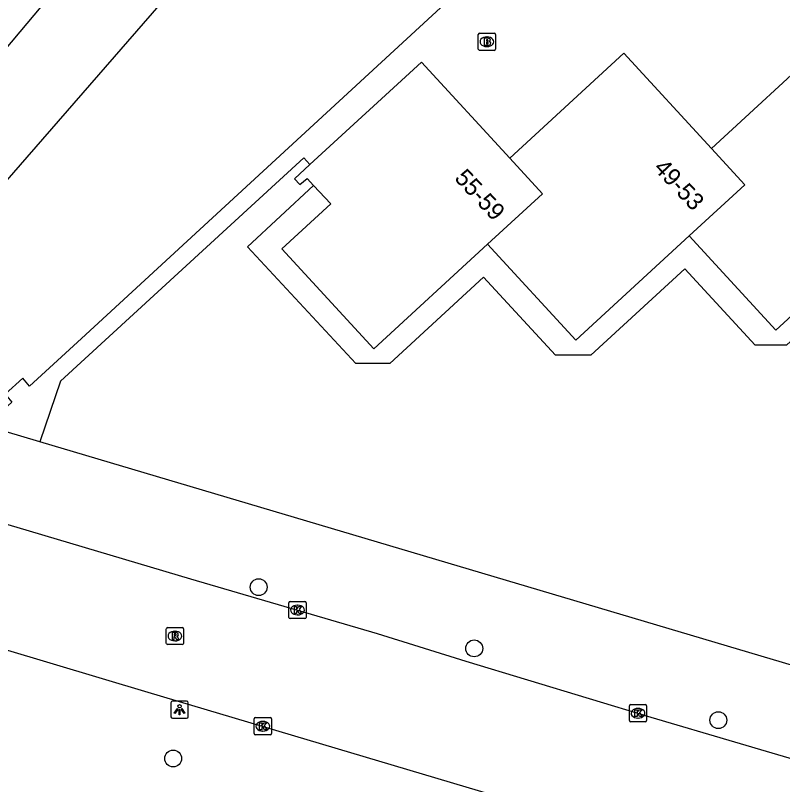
# Model space of a CAD drawing. Extents: x 160356 to 161355, y 381727 to 382845.
# Drawn here: x 160703.22 to 160747.73, y 381896.03 to 381940.67 of the extents above; entities that cross this region are included whole.
import ezdxf

# ---------------------------------------------------------------- set-up
doc = ezdxf.new("R2010")
doc.units = 0
for name, color, linetype in [('IMGEO_Boom', 7, 'Continuous'), ('IMGEO_Brandkraan', 7, 'Continuous'), ('IMGEO_Groenvoorziening', 7, 'Continuous'), ('IMGEO_Kolk', 7, 'Continuous'), ('IMGEO_Lichtpunt', 7, 'Continuous'), ('IMGEO_Pand', 7, 'Continuous'), ('IMGEO_Pand_nummerreeks', 7, 'Continuous'), ('IMGEO_Rijbaan_lokaal_open', 7, 'Continuous'), ('IMGEO_Rioolput', 7, 'Continuous'), ('IMGEO_Voetpad_halfverhard', 7, 'Continuous'), ('IMGEO_Voetpad_open', 7, 'Continuous')]:
    doc.layers.add(name, color=color, linetype=linetype)

msp = doc.modelspace()

# ---------------------------------------------------------------- linework, layer by layer
at = {"layer": 'IMGEO_Boom'}
for centre in [(160717.337, 381907.486), (160729.844, 381903.936), (160744.006, 381899.77), (160712.376, 381897.548)]:
    msp.add_circle(centre, 0.489, dxfattribs=at)
at = {"layer": 'IMGEO_Brandkraan'}
for p, q in [((160730.081, 381938.714), (160730.081, 381939.566)), ((160730.156, 381939.64), (160731.008, 381939.64)), ((160731.082, 381939.566), (160731.082, 381938.714)), ((160730.569, 381939.42), (160730.594, 381939.42)), ((160731.008, 381938.64), (160730.156, 381938.64)), ((160730.592, 381938.86), (160730.567, 381938.86))]:
    msp.add_line(p, q, dxfattribs=at)
for points in [[(160730.081, 381938.714), (160730.081, 381939.566)], [(160730.156, 381939.64), (160731.008, 381939.64)], [(160731.082, 381939.566), (160731.082, 381938.714)], [(160730.429, 381939.34), (160730.429, 381938.94), (160730.642, 381938.94)], [(160730.66, 381939.34), (160730.429, 381939.34)], [(160730.608, 381939.259), (160730.554, 381939.259), (160730.554, 381939.183)], [(160730.554, 381939.183), (160730.607, 381939.183)], [(160730.616, 381939.107), (160730.554, 381939.107), (160730.554, 381939.026)], [(160731.008, 381938.64), (160730.156, 381938.64)], [(160730.554, 381939.026), (160730.616, 381939.026)]]:
    msp.add_lwpolyline(points, dxfattribs=at)
for centre, radius, start, end in [((160730.158, 381939.564), 0.0765, 91.552, 178.448), ((160730.158, 381939.564), 0.0765, 91.552, 178.448), ((160731.006, 381939.564), 0.0765, 1.552, 88.448), ((160731.006, 381939.564), 0.0765, 1.552, 88.448), ((160730.609, 381939.221), 0.0379, 267.8285, 90.9355), ((160730.617, 381939.066), 0.0404, 269.8759, 90.5077), ((160730.664, 381939.195), 0.145, 59.4692, 91.5367), ((160730.689, 381939.242), 0.0922, 285.5137, 58.1501), ((160730.694, 381939.05), 0.105, 301.3115, 78.989), ((160730.158, 381938.716), 0.0765, 181.552, 268.448), ((160730.158, 381938.716), 0.0765, 181.552, 268.448), ((160730.648, 381939.191), 0.251, 268.6676, 293.5347), ((160731.006, 381938.716), 0.0765, 271.552, 358.448), ((160731.006, 381938.716), 0.0765, 271.552, 358.448)]:
    msp.add_arc(centre, radius, start, end, dxfattribs=at)
for centre, major_axis, ratio, start_param, end_param in [((160730.568, 381939.14), (-0.387, 0.002), 0.722429, 4.712389, 7.853982), ((160730.593, 381939.14), (-0.39, 0.002), 0.717154, 1.570796, 4.712389)]:
    msp.add_ellipse(centre, major_axis=major_axis, ratio=ratio, start_param=start_param, end_param=end_param, dxfattribs=at)
at = {"layer": 'IMGEO_Groenvoorziening'}
msp.add_lwpolyline([(160745.256, 381970.771), (160720.104, 381951.115), (160692.7, 381919.619)], dxfattribs=at)
at = {"layer": 'IMGEO_Kolk'}
for p, q in [((160719.086, 381905.737), (160719.086, 381906.589)), ((160719.161, 381906.663), (160720.013, 381906.663)), ((160720.087, 381906.589), (160720.087, 381905.737)), ((160719.574, 381906.443), (160719.599, 381906.443)), ((160720.013, 381905.663), (160719.161, 381905.663)), ((160719.597, 381905.883), (160719.572, 381905.883)), ((160738.92, 381900.675), (160739.772, 381900.675)), ((160738.845, 381899.749), (160738.845, 381900.601)), ((160739.333, 381900.455), (160739.358, 381900.455)), ((160739.846, 381900.601), (160739.846, 381899.749)), ((160717.074, 381898.994), (160717.074, 381899.846)), ((160717.149, 381899.92), (160718.001, 381899.92)), ((160718.075, 381899.846), (160718.075, 381898.994)), ((160739.356, 381899.895), (160739.331, 381899.895)), ((160717.562, 381899.7), (160717.587, 381899.7)), ((160739.772, 381899.675), (160738.92, 381899.675)), ((160718.001, 381898.92), (160717.149, 381898.92)), ((160717.585, 381899.14), (160717.56, 381899.14))]:
    msp.add_line(p, q, dxfattribs=at)
for points in [[(160719.086, 381905.737), (160719.086, 381906.589)], [(160719.161, 381906.663), (160720.013, 381906.663)], [(160720.087, 381906.589), (160720.087, 381905.737)], [(160719.407, 381906.363), (160719.53, 381906.363), (160719.53, 381906.212), (160719.66, 381906.363), (160719.824, 381906.363), (160719.678, 381906.212), (160719.831, 381905.963), (160719.679, 381905.963), (160719.594, 381906.127), (160719.53, 381906.06), (160719.53, 381905.963), (160719.407, 381905.963), (160719.407, 381906.363)], [(160720.013, 381905.663), (160719.161, 381905.663)], [(160738.92, 381900.675), (160739.772, 381900.675)], [(160738.845, 381899.749), (160738.845, 381900.601)], [(160739.166, 381900.375), (160739.289, 381900.375), (160739.289, 381900.224), (160739.419, 381900.375), (160739.583, 381900.375), (160739.437, 381900.224), (160739.59, 381899.975), (160739.438, 381899.975), (160739.353, 381900.139), (160739.289, 381900.072), (160739.289, 381899.975), (160739.166, 381899.975), (160739.166, 381900.375)], [(160739.846, 381900.601), (160739.846, 381899.749)], [(160717.074, 381898.994), (160717.074, 381899.846)], [(160717.149, 381899.92), (160718.001, 381899.92)], [(160718.075, 381899.846), (160718.075, 381898.994)], [(160717.395, 381899.62), (160717.518, 381899.62), (160717.518, 381899.469), (160717.648, 381899.62), (160717.812, 381899.62), (160717.666, 381899.469), (160717.819, 381899.22), (160717.667, 381899.22), (160717.582, 381899.384), (160717.518, 381899.317), (160717.518, 381899.22), (160717.395, 381899.22), (160717.395, 381899.62)], [(160739.772, 381899.675), (160738.92, 381899.675)], [(160718.001, 381898.92), (160717.149, 381898.92)]]:
    msp.add_lwpolyline(points, dxfattribs=at)
for centre, start, end in [((160719.163, 381906.587), 91.552, 178.448), ((160719.163, 381906.587), 91.552, 178.448), ((160720.011, 381906.587), 1.552, 88.448), ((160720.011, 381906.587), 1.552, 88.448), ((160719.163, 381905.739), 181.552, 268.448), ((160719.163, 381905.739), 181.552, 268.448), ((160720.011, 381905.739), 271.552, 358.448), ((160720.011, 381905.739), 271.552, 358.448), ((160738.922, 381900.599), 91.552, 178.448), ((160738.922, 381900.599), 91.552, 178.448), ((160739.77, 381900.599), 1.552, 88.448), ((160739.77, 381900.599), 1.552, 88.448), ((160717.151, 381899.844), 91.552, 178.448), ((160717.151, 381899.844), 91.552, 178.448), ((160717.999, 381899.844), 1.552, 88.448), ((160717.999, 381899.844), 1.552, 88.448), ((160738.922, 381899.751), 181.552, 268.448), ((160738.922, 381899.751), 181.552, 268.448), ((160739.77, 381899.751), 271.552, 358.448), ((160739.77, 381899.751), 271.552, 358.448), ((160717.151, 381898.996), 181.552, 268.448), ((160717.151, 381898.996), 181.552, 268.448), ((160717.999, 381898.996), 271.552, 358.448), ((160717.999, 381898.996), 271.552, 358.448)]:
    msp.add_arc(centre, 0.0765, start, end, dxfattribs=at)
for centre, major_axis, ratio, start_param, end_param in [((160719.573, 381906.163), (-0.387, 0.002), 0.722429, 4.712389, 7.853982), ((160719.598, 381906.163), (-0.39, 0.002), 0.717154, 1.570796, 4.712389), ((160739.332, 381900.175), (-0.387, 0.002), 0.722429, 4.712389, 7.853982), ((160739.357, 381900.175), (-0.39, 0.002), 0.717154, 1.570796, 4.712389), ((160717.561, 381899.42), (-0.387, 0.002), 0.722429, 4.712389, 7.853982), ((160717.586, 381899.42), (-0.39, 0.002), 0.717154, 1.570796, 4.712389)]:
    msp.add_ellipse(centre, major_axis=major_axis, ratio=ratio, start_param=start_param, end_param=end_param, dxfattribs=at)
at = {"layer": 'IMGEO_Lichtpunt'}
for p, q in [((160712.25, 381900.781), (160712.25, 381899.974)), ((160712.25, 381900.781), (160712.25, 381899.974)), ((160713.152, 381900.876), (160712.344, 381900.876)), ((160713.152, 381900.876), (160712.344, 381900.876)), ((160713.246, 381899.974), (160713.246, 381900.781)), ((160713.246, 381899.974), (160713.246, 381900.781)), ((160712.344, 381899.88), (160713.152, 381899.88)), ((160712.344, 381899.88), (160713.152, 381899.88))]:
    msp.add_line(p, q, dxfattribs=at)
for points in [[(160712.624, 381900.445), (160712.663, 381900.417), (160712.475, 381900.155), (160712.437, 381900.182), (160712.624, 381900.445)], [(160712.726, 381900.397), (160712.773, 381900.397), (160712.773, 381900.075), (160712.726, 381900.075), (160712.726, 381900.397)], [(160712.836, 381900.417), (160712.874, 381900.444), (160713.061, 381900.182), (160713.022, 381900.154), (160712.836, 381900.417)]]:
    msp.add_lwpolyline(points, dxfattribs=at)
msp.add_circle((160712.749, 381900.579), 0.0994, dxfattribs=at)
for centre, start, end in [((160712.344, 381900.781), 90, 180), ((160712.344, 381900.781), 90, 180), ((160713.152, 381900.781), 0, 90), ((160713.152, 381900.781), 0, 90), ((160712.344, 381899.974), 180, 270), ((160712.344, 381899.974), 180, 270), ((160713.152, 381899.974), 270, 0), ((160713.152, 381899.974), 270, 360)]:
    msp.add_arc(centre, 0.0946, start, end, dxfattribs=at)
at = {"layer": 'IMGEO_Pand'}
for points in [[(160743.604, 381932.949), (160750.211, 381939.027), (160755.254, 381933.544)], [(160731.902, 381932.381), (160738.523, 381938.472), (160743.604, 381932.949)], [(160731.902, 381932.381), (160726.776, 381937.953), (160720.314, 381932.008)], [(160743.604, 381932.949), (160745.541, 381930.843), (160742.314, 381927.875)], [(160730.608, 381927.39), (160733.796, 381930.323), (160731.902, 381932.381)], [(160720.314, 381932.008), (160719.425, 381931.19), (160719.729, 381930.86), (160720.149, 381931.202), (160720.526, 381930.796)], [(160720.526, 381930.796), (160721.52, 381929.726), (160718.69, 381927.123), (160724.02, 381921.329), (160730.608, 381927.39)], [(160753.932, 381928.46), (160747.348, 381922.403), (160742.314, 381927.875)], [(160742.314, 381927.875), (160735.732, 381921.82), (160730.608, 381927.39)]]:
    msp.add_lwpolyline(points, dxfattribs=at)
at = {"layer": 'IMGEO_Rijbaan_lokaal_open'}
for points in [[(160679.993, 381917.834), (160691.804, 381914.329), (160703.301, 381910.962), (160713.383, 381907.976), (160724.219, 381904.806), (160729.348, 381903.194), (160740.094, 381899.948), (160744.941, 381898.519), (160820.691, 381876.187), (160826.955, 381874.36)], [(160824.304, 381867.688), (160819.275, 381869.125), (160815.643, 381870.203), (160710.934, 381901.384), (160677.174, 381911.473)]]:
    msp.add_lwpolyline(points, dxfattribs=at)
at = {"layer": 'IMGEO_Rioolput'}
for p, q in [((160712.055, 381905.155), (160712.907, 381905.155)), ((160711.98, 381904.229), (160711.98, 381905.081)), ((160712.468, 381904.935), (160712.493, 381904.935)), ((160712.981, 381905.081), (160712.981, 381904.229)), ((160712.491, 381904.375), (160712.466, 381904.375)), ((160712.907, 381904.155), (160712.055, 381904.155))]:
    msp.add_line(p, q, dxfattribs=at)
for points in [[(160712.055, 381905.155), (160712.907, 381905.155)], [(160711.98, 381904.229), (160711.98, 381905.081)], [(160712.569, 381904.853), (160712.317, 381904.855), (160712.317, 381904.455)], [(160712.495, 381904.774), (160712.441, 381904.774), (160712.441, 381904.693)], [(160712.441, 381904.693), (160712.493, 381904.693)], [(160712.981, 381905.081), (160712.981, 381904.229)], [(160712.317, 381904.455), (160712.441, 381904.455), (160712.441, 381904.617), (160712.452, 381904.617)], [(160712.499, 381904.588), (160712.57, 381904.455), (160712.71, 381904.455), (160712.645, 381904.581)], [(160712.907, 381904.155), (160712.055, 381904.155)]]:
    msp.add_lwpolyline(points, dxfattribs=at)
for centre, radius, start, end in [((160712.057, 381905.079), 0.0765, 91.552, 178.448), ((160712.057, 381905.079), 0.0765, 91.552, 178.448), ((160712.905, 381905.079), 0.0765, 1.552, 88.448), ((160712.905, 381905.079), 0.0765, 1.552, 88.448), ((160712.477, 381904.882), 0.19, 274.7715, 282.9687), ((160712.501, 381904.678), 0.0964, 77.0061, 93.1865), ((160712.515, 381904.735), 0.0378, 276.6634, 79.6772), ((160712.568, 381904.743), 0.109, 350.3612, 89.416), ((160712.566, 381904.743), 0.112, 277.5842, 350.9817), ((160712.057, 381904.231), 0.0765, 181.552, 268.448), ((160712.057, 381904.231), 0.0765, 181.552, 268.448), ((160712.451, 381904.564), 0.0533, 26.0293, 88.6989), ((160712.55, 381904.528), 0.108, 29.5134, 73.7905), ((160712.905, 381904.231), 0.0765, 271.552, 358.448), ((160712.905, 381904.231), 0.0765, 271.552, 358.448)]:
    msp.add_arc(centre, radius, start, end, dxfattribs=at)
for centre, major_axis, ratio, start_param, end_param in [((160712.467, 381904.655), (-0.387, 0.002), 0.722429, 4.712389, 7.853982), ((160712.492, 381904.655), (-0.39, 0.002), 0.717154, 1.570796, 4.712389)]:
    msp.add_ellipse(centre, major_axis=major_axis, ratio=ratio, start_param=start_param, end_param=end_param, dxfattribs=at)
at = {"layer": 'IMGEO_Voetpad_halfverhard'}
for points in [[(160687.876, 381921.119), (160713.126, 381951.198)], [(160781.317, 381931.671), (160771.659, 381922.705), (160769.498, 381922.705), (160765.386, 381927.176), (160759.961, 381922.185), (160757.648, 381922.185), (160753.532, 381926.659), (160747.962, 381921.535), (160746.136, 381921.535), (160742.065, 381925.96), (160736.612, 381920.943), (160734.554, 381920.943), (160730.387, 381925.473), (160724.948, 381920.47), (160722.977, 381920.47), (160716.693, 381927.236), (160720.526, 381930.796)]]:
    msp.add_lwpolyline(points, dxfattribs=at)
at = {"layer": 'IMGEO_Voetpad_open'}
for points in [[(160726.588, 381943.368), (160727.68, 381942.609), (160728.881, 381942.036), (160707.061, 381921.911), (160704.036, 381919.156), (160703.65, 381919.616), (160702.637, 381918.693), (160703.013, 381918.224), (160701.529, 381916.873)], [(160720.314, 381932.008), (160719.952, 381932.403), (160705.831, 381919.449), (160704.645, 381915.916)], [(160704.645, 381915.916), (160702.632, 381916.514), (160701.529, 381916.873)], [(160771.213, 381896.146), (160770.721, 381896.291), (160746.482, 381903.49), (160704.645, 381915.916)]]:
    msp.add_lwpolyline(points, dxfattribs=at)

# ---------------------------------------------------------------- texts
at = {"layer": 'IMGEO_Pand_nummerreeks'}
for s, rotation, p in [('49-53', 313.0475, (160740.206, 381931.767)), ('55-59', 313.0461, (160728.65, 381931.181))]:
    msp.add_text(s, height=1, rotation=rotation, dxfattribs=at).set_placement(p)

doc.saveas('drawing.dxf')
